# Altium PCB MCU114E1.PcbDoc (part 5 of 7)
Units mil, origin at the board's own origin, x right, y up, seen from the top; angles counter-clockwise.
Board outline 4163.97 x 2322.49 mil, 8 copper layers (Top Layer, GND 2, Signal Layer 3, Power 4, Power 5, Signal Layer 6, GND 7, Bottom), stack 61.2 mil thick; 444 components, 416 nets, 1812 pads, 989 vias.
Unrouted connection lines stored in the file: 3.
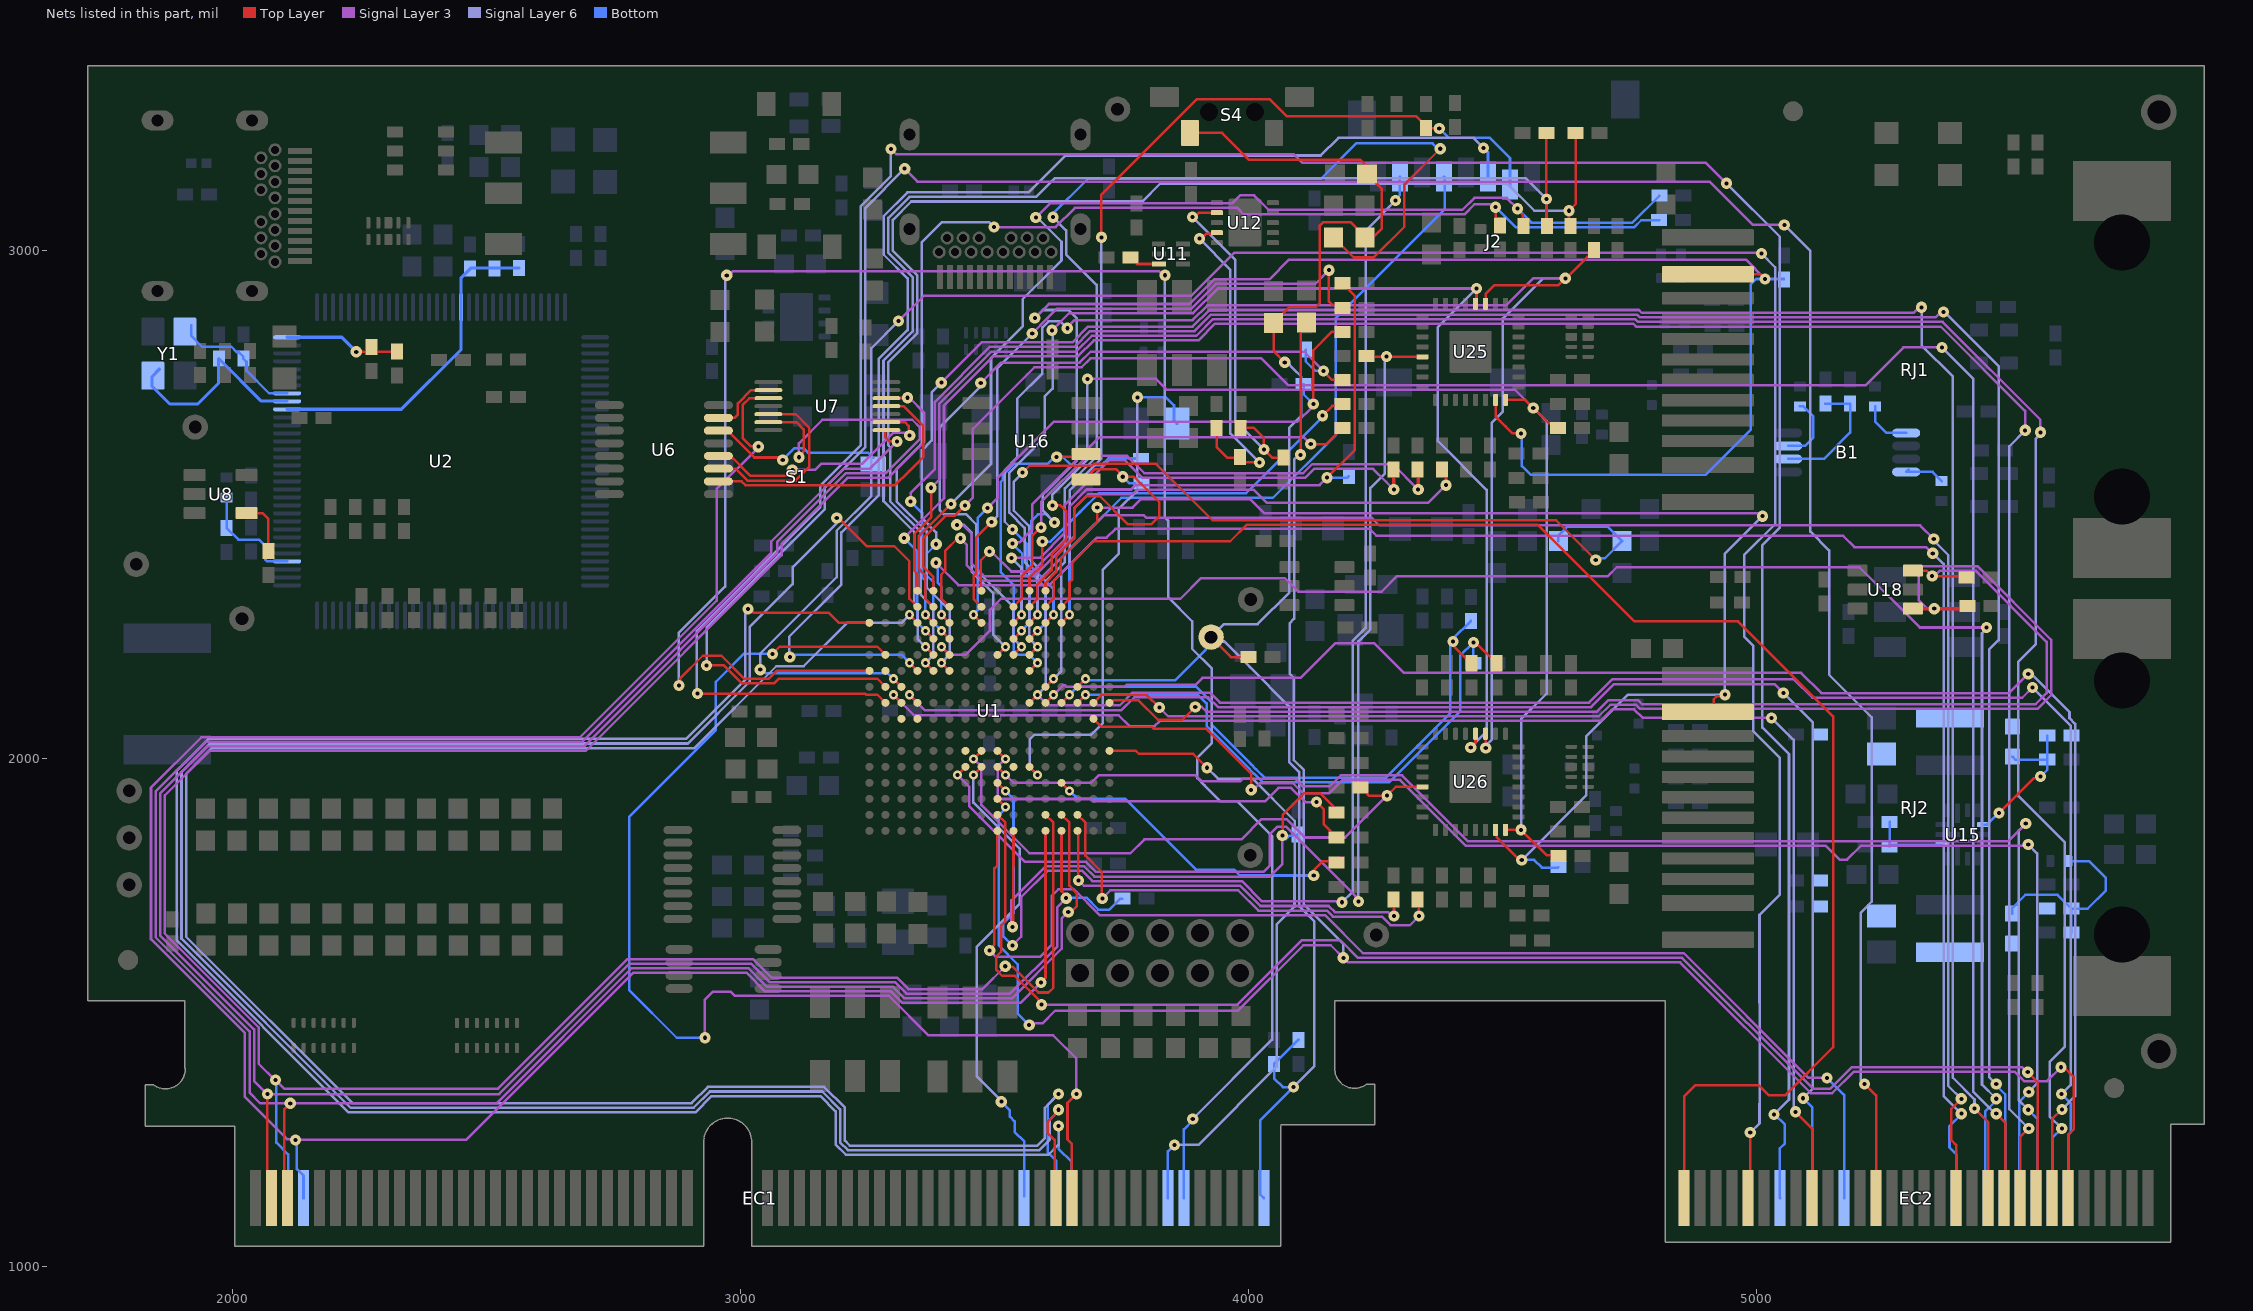
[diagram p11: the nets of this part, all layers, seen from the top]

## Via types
v1: diameter 22, hole 8, Top Layer to Bottom, tented both sides, 818 vias
v2: diameter 18, hole 8, Top Layer to Bottom, tented both sides, 153 vias
v3: diameter 19.68, hole 7.87, Top Layer to Bottom, 18 vias

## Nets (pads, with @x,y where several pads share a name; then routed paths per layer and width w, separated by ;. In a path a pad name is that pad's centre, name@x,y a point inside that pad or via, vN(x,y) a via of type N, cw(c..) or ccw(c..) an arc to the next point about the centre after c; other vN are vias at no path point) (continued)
MCU_GPIO88: EC2.155 U1.B6 | length 3538.7
  Top Layer w5: U1.B6@3411.08,2299.01 3394.54,2315.55 3394.96,2315.96 3394.96,2362.39 3403,2370.44 3403,2409.44 3427.45,2433.89 v1(3432.54,2433.89) ; EC2.155@5391.91,1135.27 5391.91,1240.19 5382.33,1249.77 5382.33,1311.09 v1(5402.04,1330.8)
  Signal Layer 3 w5: v1(3432.54,2433.89) 3445,2421.43 3445,2380.9 3475.44,2350.45 3586.4,2350.45 3715.47,2479.52 3792.83,2479.52 3798.58,2473.77 4242.27,2473.77 4256.77,2459.27 5320.83,2459.27 v1(5347.83,2432.27)
  Signal Layer 6 w5: v1(5347.83,2432.27) 5347.83,2429.02 5376.37,2400.48 5376.37,1356.47 v1(5402.04,1330.8)
MCU_GPIO89: EC2.156 U1.C6 | length 3477.8
  Top Layer w5: v2(3395.33,2283.26) U1.C6@3411.08,2267.52
  Signal Layer 3 w5: v1(3384.42,2385.68) 3428.65,2341.45 3608.02,2341.45 3701.56,2435 3720.45,2435 3737.72,2452.27 4237.83,2452.27 4251.33,2438.77 5169.33,2438.77 5191.83,2416.27 5332.4,2416.27 5344.4,2404.27 v1(5345.83,2404.27)
  Signal Layer 6 w5: v1(5345.83,2404.27) 5346.29,2404.27 5367.37,2383.19 5367.37,1335.98 v1@5399.83,1303.52
  Bottom w5: v1@3388.36,2385.68 3388.36,2346.15 3395.33,2339.18 v2(3395.33,2283.26) ; EC2.156@5391.91,1135.27 5391.91,1222.19 5378.83,1235.27 5378.83,1277.27 5402.04,1300.48 v1(5402.04,1301.54)
MCU_GPIO90: EC2.159 U1.D6 | length 4359.8
  Top Layer w5: v2(3395.33,2251.77) U1.D6@3411.08,2236.02 ; v1(5428,1311.82) 5454.91,1284.92 EC2.159@5454.91,1135.27
  Signal Layer 3 w5: v1(3395,2740) 3474.27,2819.27 3653,2819.27 3684,2850.27 3889.65,2850.27 3922.38,2883 4767.76,2883 4773.31,2877.45 5308.42,2877.45 5319.23,2888.27 v1(5323.83,2888.27)
  Signal Layer 6 w5: v1(3385,2422) 3385,2445.4 3356.83,2473.57 3356.83,2606.83 3375.87,2625.87 3375.87,2720.87 v1(3395,2740) ; v1(5323.83,2888.27) 5323.83,2813.27 5385.37,2751.73 5385.37,1372.27 5428,1329.64 v1(5428,1311.82)
  Bottom w5: v1(3385,2422) 3366.4,2403.4 3366.4,2360.6 3379.33,2347.67 3379.33,2267.76 v2(3395.33,2251.77)
MCU_GPIO91: EC2.160 U1.E6 | length 3393.4
  Top Layer w5: v2(3395.33,2220.27) U1.E6@3411.08,2204.52
  Signal Layer 3 w5: v2(3395.33,2220.27) 3410.83,2204.77 3443.42,2204.77 3490.82,2252.17 3490.82,2292.84 3512.75,2314.77 3865.58,2314.77 3906.13,2355.31 3930.88,2355.31 4070.83,2355.32 4097.6,2328.54 4261.38,2328.54 4292.1,2359.27 4706.56,2359.27 4724.06,2376.77 5202.08,2376.77 5320.58,2258.27 v1(5451.83,2258.27)
  Signal Layer 6 w5: v1(5451.83,2258.27) 5451.83,2255.84 5442.83,2246.84 5442.83,1358.94 v1(5470.83,1330.94)
  Bottom w5: EC2.160@5454.91,1135.27 5449.05,1141.12 5449.05,1305.49 v1@5467.83,1324.27
MCU_GPIO92: EC2.161 U1.A5 | length 4123.5
  Top Layer w5: U1.A5@3379.58,2330.51 3379.58,2357.52 3359.83,2377.27 3359.83,2434.54 3403.11,2477.82 3421.39,2477.82 v1(3441.83,2498.27) ; v1(5470.83,1301.6) 5488.33,1284.1 5488.33,1135.27 EC2.161@5486.4,1135.27
  Signal Layer 3 w5: v1(3441.83,2498.27) 3457.33,2513.77 3457.33,2649.33 3578.27,2770.27 3671,2770.27 3688.5,2787.77 3873.97,2787.77 4024.96,2787.77 4077.96,2734.77 5213.77,2734.77 5288.27,2809.27 v1(5363.83,2809.27)
  Signal Layer 6 w5: v1(5363.83,2809.27) 5425.83,2747.27 5425.83,1344.54 5468.77,1301.6 v1(5470.83,1301.6)
MCU_GPIO93: EC2.162 U1.C5 | length 4348.2
  Top Layer w5: v2(3363.83,2283.26) U1.C5@3379.58,2267.52
  Signal Layer 3 w5: v1(3334.83,2506.27) 3334.83,2522.87 3382.33,2570.37 3382.33,2702.33 3490.27,2810.27 3552.37,2810.27 3656.72,2810.27 3687.72,2841.27 3893.38,2841.27 3926.11,2874 4764.03,2874 4769.58,2868.45 5351.42,2868.45 5362.23,2879.27 v1(5366.83,2879.27)
  Signal Layer 6 w5: v1(5366.83,2879.27) 5368.83,2879.27 5475.37,2772.73 5475.37,2233.54 5456.94,2215.1 5456.94,1374.16 v1(5470.83,1360.27)
  Bottom w5: v1(3334.83,2506.27) 3357.4,2483.7 3357.4,2356.88 3363.83,2350.44 v2(3363.83,2283.26) ; v1@5467.83,1360.27 5488.33,1339.77 5488.33,1137.2 EC2.162@5486.4,1135.27
MCU_GPIO94: EC2.163 U1.D5 | length 4365.5
  Top Layer w5: v2(3363.83,2251.77) U1.D5@3379.58,2236.02 ; EC2.163@5517.9,1135.27 5517.9,1255.33 v1(5534.83,1272.27)
  Signal Layer 3 w5: v1(3322,2434) 3322,2434.19 3400.33,2512.52 3400.33,2694.88 3497.73,2792.27 3544.92,2792.27 3664.18,2792.27 3695.18,2823.27 3900.83,2823.27 3933.56,2856 4756.58,2856 4762.12,2850.45 5361.65,2850.45 5527.83,2684.27 v1(5527.83,2646.27)
  Signal Layer 6 w5: v1(5527.83,2646.27) 5496.37,2614.8 5496.37,1310.73 v1(5534.83,1272.27)
  Bottom w5: v1(3322,2434) 3347.84,2408.16 3347.84,2267.76 v2(3363.83,2251.77)
MCU_GPIO95: EC2.168 U1.A4 | length 4326.5
  Top Layer w5: U1.A4@3348.09,2330.51 3348.09,2363.56 3341.83,2369.81 3341.83,2442 3374.83,2475 v1(3374.83,2533.27)
  Signal Layer 3 w5: v1(3374.83,2533.27) 3391.33,2549.77 3391.33,2698.6 3494,2801.27 3548.65,2801.27 3660.45,2801.27 3691.45,2832.27 3897.1,2832.27 3929.83,2865 4760.3,2865 4765.85,2859.45 5365.37,2859.45 5557.83,2667 v1(5557.83,2642.27)
  Signal Layer 6 w5: v1(5557.83,2642.27) 5557.83,2638.34 5548.33,2628.84 5548.33,2225.02 5514.37,2191.06 5514.37,1926.36 5605.83,1834.9 5605.83,1433.5 5575.83,1403.5 5575.83,1296.27 v1(5599.83,1272.27)
  Bottom w5: EC2.168@5580.89,1135.27 5580.89,1253.33 v1(5599.83,1272.27)
MCU_GPIO96: EC1.93 U1.B4 | length 4396.5
  Top Layer w5: v1(3189.35,2473.79) 3193.04,2473.79 3248.27,2418.55 3302.45,2418.55 3331.96,2389.04 3331.96,2324.14 3331.96,2315.13 U1.B4@3348.09,2299.01 ; EC1.93@3620.35,1135.27 3617.83,1137.79 3617.83,1250.23 3604.33,1263.73 3604.33,1285.15 3625.83,1306.65 v1(3625.83,1309.27)
  Signal Layer 6 w5: v1(3189.35,2473.79) 3187.88,2472.31 3187.88,2462.06 3102.33,2376.52 3102.33,2343.52 3017.83,2259.02 3017.83,2151.54 2896.29,2030 1956.46,2030 1900,1973.54 1900,1645.98 2232.72,1313.27 2907.54,1313.27 2939.54,1345.27 3160.77,1345.27 3196.13,1309.91 3196.13,1244.84 3211.21,1229.77 3587.86,1229.77 3608.29,1250.2 3608.29,1289.1 3625.83,1306.65 v1(3625.83,1309.27)
MCU_GPIO97: EC1.94 U1.C4 | length 4145.2
  Top Layer w5: v2(3332.34,2283.26) U1.C4@3348.09,2267.52
  Signal Layer 6 w5: v2(3332.34,2283.26) 3316.59,2267.51 3209.83,2267.51 3124.31,2182 3070.31,2182 2909.31,2021 1960.18,2021 1909,1969.82 1909,1649.71 2236.44,1322.27 2903.81,1322.27 2935.81,1354.27 3164.5,1354.27 3205.13,1313.64 3205.13,1248.57 3214.93,1238.77 3584.13,1238.77 3598.83,1253.47 3598.83,1313.27 v1(3625.83,1340.27)
  Bottom w5: EC1.94@3620.35,1135.27 3620.83,1135.74 3620.83,1209.27 3604.33,1225.77 3604.33,1318.77 v1(3625.83,1340.27)
MCU_GPIO98: EC1.95 U1.E2 | length 2387.3
  Top Layer w5: v1(3062.83,2206.27) 3077.21,2220.65 3268.97,2220.65 U1.E2@3285.09,2204.52 ; EC1.95@3651.85,1135.27 3651.85,1242.25 3643.33,1250.77 3643.33,1322.77 v1(3660.83,1340.27)
  Signal Layer 3 w5: v1(2930,1451) 2930,1526.19 2945.58,1541.77 2980.5,1541.77 2989,1533.27 3292.58,1533.27 3370.08,1455.77 3615.33,1455.77 3660.83,1410.27 v1(3660.83,1340.27)
  Bottom w5: v1(2930,1451) 2874.46,1451 2780.73,1544.73 2780.73,1885.63 2951.33,2056.24 2951.33,2151.51 3006.09,2206.27 v1(3062.83,2206.27)
MCU_GPIO99: EC1.96 U1.C1 | length 4098.7
  Top Layer w5: v1(3014.84,2294.37) 3019.08,2294.37 3026.27,2287.19 3173.94,2287.19 3193.61,2267.51 U1.C1@3253.6,2267.52
  Signal Layer 6 w5: v1(3014.84,2294.37) 3014.84,2289.77 3008.83,2283.76 3008.83,2155.27 2892.56,2039 1952.73,2039 1891,1977.27 1891,1642.26 2228.99,1304.27 2911.27,1304.27 2943.27,1336.27 3157.05,1336.27 3187.13,1306.18 3187.13,1241.11 3207.48,1220.77 3605.76,1220.77 3625.79,1240.8 v1(3625.79,1277.47) v1@3625.79,1281.86
  Bottom w5: v1@3625.83,1281.81 3625.83,1232.17 3651.85,1206.15 EC1.96@3651.85,1135.27
MCU_GPIO100: J2.3 U1.F4 | length 2558.4
  Top Layer w5: v2(3332.34,2188.77) U1.F4@3348.09,2173.03
  Signal Layer 6 w5: v1@3095.87,2203.69 3095.87,2240.31 3198.33,2342.77 3198.33,2445.29 3272.33,2519.29 3272.33,2787.33 3328.6,2843.6 3328.6,2944.94 3281.83,2991.71 3281.83,3067.83 3328.5,3114.5 3566.5,3114.5 3639,3187 4141.56,3187 4176.33,3221.77 4442.23,3221.77 v1(4462,3202)
  Bottom w5: v1(3096.91,2200.46) 3100.16,2203.72 3107.28,2203.72 3108.34,2204.77 3316.34,2204.77 v2(3332.34,2188.77) ; v1(4462,3202) 4470.75,3193.25 J2.3@4470.75,3145.39
MCU_GPIO101: J2.7 U1.N9 | length 2603.9
  Top Layer w5: U1.N9@3505.57,1952.55 3520.87,1937.25 v2@3520.87,1936.69
  Signal Layer 3 w5: v1(3534.83,1632.69) 3535.12,1632.69 3552.33,1649.89 3552.33,1727.77 3603.75,1779.19 3672.54,1779.19 3692.54,1759.19 3986.54,1759.19 4026.46,1719.27 4182.12,1719.27 v1(4183.76,1717.64)
  Signal Layer 6 w5: v1(4183.76,1717.64) 4204.33,1738.21 4204.33,2232.05 4230.33,2258.05 4230.33,3039.77 v1(4288.83,3098.27)
  Bottom w5: v2(3521.31,1936.81) 3537.06,1921.06 3537.06,1900.78 3537.04,1894.54 ; v1(3534.83,1632.69) 3517.33,1650.19 3517.33,1676.52 3537.06,1696.25 3537.06,1894.52 ; v1(4288.83,3098.27) 4288.83,3100.36 4297.52,3109.05 J2.7@4297.52,3145.39
MCU_GPIO102: J2.5 U1.C13 | length 1365.7
  Top Layer w5: U1.C13@3631.55,2267.52 v2(3647.3,2283.26)
  Bottom w5: v2(3647.3,2283.26) 3647.3,2411.35 3749.09,2513.14 4047.27,2513.14 4171.33,2637.2 4171.33,2798.52 4171.33,2867.33 4385.83,3081.83 4385.83,3099.27 4385.83,3143.7 J2.5@4384.14,3145.39
MCU_GPIO103: J2.2 R36.1 U1.G12 | length 1998.6
  Top Layer w5: U1.G12@3600.06,2141.53 v2(3615.8,2157.28) ; v1(3710,3026) 3710,3109.89 3898.11,3298 4040.81,3298 4074.5,3264.31 4329.2,3264.31 4348.51,3245 R36.1@4348.51,3241.06 4349.31,3240.27 v1(4374.83,3240.27)
  Signal Layer 6 w5: v2(3615.8,2157.28) 3631.3,2172.78 3631.3,2365.42 3647.33,2381.45 3647.33,2527.99 3709.83,2590.49 3709.83,2964.32 3710,2964.49 v1(3710,3026)
  Bottom w5: v1(4374.83,3240.27) 4392.83,3222.27 4473.73,3222.27 4514.06,3181.94 J2.2@4514.06,3129.65
MCU_GPIO104: EC2.121 U1.B13 | length 2980.9
  Top Layer w5: U1.B13@3631.55,2299.01 3647.31,2314.77 3647.3,2347.31 3653.08,2353.09 3653.08,2386.52 3694.56,2428 3963.58,2428 3995.85,2460.27 4568.73,2460.27 4758.73,2270.27 4962.83,2270.27 5149.83,2083.27 5149.83,1432.27 5055.83,1338.27 5022.83,1338.27 5003.18,1357.92 4878.83,1357.92 4856.48,1335.57 EC2.121@4856.48,1135.27
MCU_GPIO105: EC1.108 U1.L16 | length 1295.1
  Top Layer w5: U1.L16@3726.04,2015.55 3777.8,2015.55 3783.58,2009.77 3858.08,2009.77 3890.33,2009.77 v1(3917.83,1982.27)
  Signal Layer 6 w5: v1(3853.83,1240.27) 3901.27,1240.27 4055,1394 4055,1674 4090,1709 4090,1768 4090.33,1768.33 4090.33,1877.99 4007.55,1960.77 3939.33,1960.77 v1(3917.83,1982.27)
  Bottom w5: EC1.108@3840.83,1135.27 3840.83,1227.26 v1(3853.83,1240.27)
MCU_GPIO106: EC1.110 U1.F1 | length 4164.9
  Top Layer w5: v1(2878.83,2144.27) 2881.13,2146.57 2881.13,2158.13 2925.65,2202.65 2962.35,2202.65 3007.81,2157.19 3055.19,2157.19 3071,2173 3225.56,2173 ; 3225.59,2173.03 U1.F1@3253.6,2173.03
  Signal Layer 3 w5: v1(2972.83,2951.27) 2976.53,2951.27 2984.26,2959 3190.25,2959 3190.75,2959.5 3205.25,2959.5 3205.75,2959 3823.84,2959 3831.53,2951.31 v1(3835.27,2951.31)
  Signal Layer 6 w5: v1(2878.83,2144.27) 2878.83,2248.15 2969.5,2338.82 2969.5,2939.84 2969.58,2939.92 2969.58,2948.02 v1(2972.83,2951.27) ; v1(3835.27,2951.31) 3834.65,2950.7 3834.65,2475.17 3842,2467.83 3842,2317.1 3888.83,2270.27 3888.83,2216.02 3927.33,2177.52 3927.33,2031.02 3898.96,2002.65 3898.96,1961.89 3913.33,1947.52 3944.58,1916.27 3977.56,1916.27 4046,1847.83 4046,1447.44 v1(3889.83,1291.27)
  Bottom w5: EC1.110@3872.32,1135.27 3872.32,1270.76 3889.83,1288.27 v1(3889.83,1291.27)
MCU_GPIO107: U1.F2
MCU_GPIO108: EC2.145 U1.G2 | length 5300.7
  Top Layer w5: v1(2933.23,2183.63) 2967.37,2183.63 3002.81,2148.19 3066.17,2148.19 3075.64,2157.65 3268.97,2157.65 U1.G2@3285.09,2141.53 ; v1(5211.83,1360.27) 5234.43,1337.67 EC2.145@5234.43,1135.27
  Signal Layer 3 w5: v1(3323,3161) 3348.23,3135.77 4906.33,3135.77 4991.83,3050.27 v1(5053.83,3050.27)
  Signal Layer 6 w5: v1(2933.23,2183.63) 2933.23,2258.42 3166,2491.19 3166,2534 3245.68,2613.68 3245.68,3083.68 v1(3323,3161) ; v1(5053.83,3050.27) 5105,2999.1 5105,2446.85 5141.83,2410.02 5141.83,2165.27 5225.83,2081.27 5225.83,1718.81 5203.83,1696.81 5203.83,1384.27 5203.83,1368.27 v1(5211.83,1360.27)
MCU_GPIO109: EC2.129 U1.G3 | length 4795.2
  Top Layer w5: v2(3300.84,2157.28) U1.G3@3316.59,2141.53 ; EC2.129@4982.46,1135.27 4986.83,1139.63 v1(4986.83,1264.27)
  Signal Layer 3 w5: v1(3311.1,2861.35) 3360.54,2910.78 3886.52,2910.78 3971.74,2996 5007,2996 v1(5009,2994)
  Signal Layer 6 w5: v1(3038.83,2175.27) 3038.83,2207.02 3189.33,2357.52 3189.33,2449.02 3257.49,2517.18 3257.49,2807.73 v1(3311.1,2861.35) ; v1(4986.83,1264.27) 5005,1282.44 5005,1320.69 5005.33,1321.02 5005.33,1519.21 5005,1519.54 5005,1692.73 5045,1732.73 5045,2001.64 4992.83,2053.81 4992.83,2222.17 4975.33,2239.67 4975.33,2401.52 5036,2462.19 5036,2967 v1(5009,2994)
  Bottom w5: v1(3038.83,2175.27) 3042.99,2175.27 3050.26,2168 3290.12,2168 v2(3300.84,2157.28)
MCU_GPIO110: EC2.134 U1.H2 | length 5382
  Top Layer w5: v1(2915.46,2128.07) 3245.32,2128.07 3247.23,2126.16 3268.97,2126.16 U1.H2@3285.09,2110.03
  Signal Layer 3 w5: v1(3296,3200) 3296.38,3200 3307.2,3189.18 4088.82,3189.18 4105.5,3172.5 4899.6,3172.5 v1(4939.83,3132.27)
  Signal Layer 6 w5: v1(2915.46,2128.07) 2913.83,2129.7 2913.83,2251.75 3157,2494.91 3157,2537.73 3236.68,2617.41 3236.68,3087.41 3296,3146.73 v1(3296,3200) ; v1(4939.83,3132.27) 5045,3027.1 5045,2454.69 5010.83,2420.52 5010.83,2061.27 5050.33,2021.77 5063,2009.1 5063,1329.44 v1(5033.83,1300.27)
  Bottom w5: v1(5033.83,1300.27) 5034.83,1300.27 5054.83,1280.27 5054.83,1243.27 5044.83,1233.27 5044.83,1135.89 EC2.134@5045.46,1135.27
MCU_GPIO111: EC2.137 U1.H3 | length 2774.7
  Top Layer w5: v2(3300.84,2125.78) U1.H3@3316.59,2110.03 ; v1(5075.83,1305.27) 5108.45,1272.65 EC2.137@5108.45,1135.27
  Signal Layer 3 w5: v2(3300.84,2125.78) 3341.1,2085.52 3743.83,2085.52 3765.36,2064 3814.83,2064 3825.41,2074.58 4692.41,2074.58 4715.1,2097.27 4758.42,2097.27 4775.42,2080.27 v1(5028.83,2080.27)
  Signal Layer 6 w5: v1(5028.83,2080.27) 5072,2037.1 5072,1316.7 5072.58,1316.12 5072.58,1308.52 v1(5075.83,1305.27)
MCU_GPIO112: EC2.138 U1.H4 | length 2832.7
  Top Layer w5: v2(3332.34,2125.78) U1.H4@3348.09,2110.03
  Signal Layer 3 w5: v2(3332.34,2125.78) 3363.09,2095.03 3748.84,2095.03 3774.81,2121 3920.27,2121 3939.69,2101.58 4673.43,2101.58 4718.85,2147 5034.1,2147 v1(5051.83,2129.27)
  Signal Layer 6 w5: v1(5051.83,2129.27) 5110,2071.1 5110,1351 v1(5091,1332)
  Bottom w5: v1(5091,1332) 5108.45,1314.55 EC2.138@5108.45,1135.27
MCU_GPIO113: U1.J3 | length 0
MCU_GPIO114: U1.J4
MCU_GPIO115: EC2.169 R212.1 U1.P9 | length 4320.1
  Top Layer w5: U1.P9@3505.57,1921.06 v2(3521.31,1905.31) ; v1(4102,2598) 4102,2846.18 R212.1@4113.87,2858.05 ; v1(5598,1393) 5604.1,1393 5623,1374.1 5623,1270.69 5612.39,1260.07 EC2.169@5612.39,1135.27
  Signal Layer 3 w5: v1(3568,1476) 3571.25,1479.25 3594.25,1479.25 3619.27,1504.27 3979,1504.27 4107.73,1633 4161.33,1633 v1(4186.06,1608.27) 4195.06,1599.27 4848.83,1599.27 5106.33,1341.77 5148.06,1341.77 5190.56,1384.27 5507.08,1384.27 5525.58,1365.77 5570.77,1365.77 v1(5598,1393)
  Signal Layer 6 w5: v1(4102,2598) 4098.68,2598 4089.33,2588.65 4089.33,2275.52 4080.33,2266.52 4080.33,2167.67 4088.59,2159.41 4088.59,1997.45 4108.33,1977.71 4108.33,1760.54 4108,1760.21 4108,1713.83 4186.06,1635.77 v1(4186.06,1608.27)
  Bottom w5: v2(3521.31,1905.31) 3521.31,1901.79 3507.8,1888.28 3507.8,1633.2 3545.4,1595.6 3545.4,1498.6 v1(3568,1476)
MCU_GPIO116: EC2.170 R78.1 U1.H11 | length 5316.3
  Top Layer w5: U1.H11@3568.56,2110.03 v2(3584.31,2125.78) ; R78.1@4168.13,3024.77 4206.63,2986.27 4245.83,2986.27 4306.33,3046.77 4306.33,3129.77 v1(4376.83,3200.27)
  Signal Layer 3 w5: v2(3584.31,2125.78) 3604.86,2105.22 3746.31,2105.22 3771.09,2130 3924,2130 3943.42,2110.58 4669.7,2110.58 4715.12,2156 5073,2156 5109,2120 5522,2120 v1(5542,2140)
  Signal Layer 6 w5: v2(3584.31,2125.78) 3600.3,2141.78 3600.3,2349.05 3638.33,2387.07 3638.33,2531.72 3700.83,2594.22 3700.83,2932.17 3640.53,2992.47 3640.53,3039.69 v1(3614.58,3065.64) ; v1(5542,2140) 5617,2065 5617,1358 v1(5599,1340)
  Bottom w5: v1@3611.11,3069.11 3683.27,3141.27 4141.83,3141.27 4211.33,3210.77 4361.73,3210.77 4372.23,3200.27 v1(4376.83,3200.27) ; v1(5599,1340) 5617.5,1321.5 5617.5,1265.19 5612.39,1260.07 EC2.170@5612.39,1135.27
MCU_GPIO119: U1.M10
MCU_GPIO120: R85.2 U1.M11 | length 1042
  Top Layer w5: U1.M11@3568.56,1984.05 v2(3584.31,1968.3)
  Signal Layer 6 w5: v2(3584.31,1968.3) 3568.81,1983.8 3568.81,2037.71 3577.89,2046.79 3685.21,2046.79 3689.63,2046.79 3712.83,2070 3712.83,2372 3744.1,2403.27 3744.1,2491.17 3780.78,2527.85 v1(3780.78,2711.18)
  Bottom w5: v1(3780.78,2711.18) 3837.07,2711.18 3852.91,2695.34 3852.91,2665.19 R85.2@3858.83,2659.27
MCU_GPIO122: U1.L7 | length 0
MCU_GPIO123: R108.2 U1.M7 U25.21 | length 2255.2
  Top Layer w5: v2(3426.83,1968.3) U1.M7@3442.57,1984.05 ; R108.2@4232.06,2792.69 4233.9,2790.84 U25.21@4341.95,2790.84
  Signal Layer 3 w5: v2(3426.83,1968.3) 3449.83,1945.3 3449.83,1907.27 3559.91,1797.19 3679.99,1797.19 3699.68,1777.5 3953.58,1777.5 3953.89,1777.19 4029,1777.19 4041.57,1789.76 4041.57,1851.77 4056.3,1866.5 4073.25,1866.5 4210.07,1729.67 ; 4210.07,1729.63 4215.83,1723.87 v1(4215.83,1719.27)
  Signal Layer 6 w5: v1(4215.83,1719.27) 4215.83,2230.82 4239.33,2254.32 4239.33,2532.77 4267.94,2561.37 4267.94,2788.37 v1(4270.83,2791.27)
MCU_GPIO124: R142.2 U1.L8 U26.21 | length 1172.1
  Top Layer w5: v2(3458.32,1999.8) U1.L8@3474.07,2015.55 ; R142.2@4219.5,1942.8 4223.44,1942.8 4232.75,1933.49 4232.75,1930.2 4235.68,1927.27 v1(4271.83,1927.27) 4289.41,1944.84 U26.21@4341.95,1944.84
  Signal Layer 3 w5: v2(3458.32,1999.8) 3473.82,1984.3 3473.82,1908.55 3568.37,1814 3767,1814 3794.45,1841.45 3985.45,1841.45 4025.27,1881.27 4074.31,1881.27 4110.54,1845.03 4189.6,1845.03 v1(4271.83,1927.27)
MCU_GPIO125: EC1.90 U1.M8 | length 964.2
  Top Layer w5: v2(3458.32,1968.3) U1.M8@3474.07,1984.05
  Signal Layer 6 w5: v2(3458.32,1968.3) 3458.32,1913.53 3549.83,1822.02 3549.83,1715.27 3464.37,1629.81 3464.37,1375.61 3513.11,1326.88 v1(3513.11,1325.18)
  Bottom w5: v1(3513.11,1325.18) 3530.03,1308.26 3530.03,1295.63 3539.33,1286.33 3539.33,1265.77 3558.43,1246.67 EC1.90@3558.43,1138.69
MCU_GPIO126: EC2.142 U1.T9 | length 2410.3
  Top Layer w5: v1(3490.3,1622.75) 3490.3,1625.11 3499.37,1634.18 3499.37,1784.02 3505.57,1790.22 U1.T9@3505.57,1858.07
  Signal Layer 3 w5: v1(3490.3,1622.75) 3502.79,1610.27 3588.83,1610.27 3612.83,1634.27 3612.83,1730.54 3625.48,1743.19 3655.81,1743.19 3706.73,1692.27 4149.83,1692.27 4224.83,1617.27 4856.29,1617.27 5101.56,1372 v1(5138,1372)
  Bottom w5: v1(5138,1372) 5171.44,1338.56 EC2.142@5171.44,1135.27
MCU_GPIO127: EC2.165 U1.R9 | length 2833.4
  Top Layer w5: U1.R9@3505.57,1889.56 3520.94,1874.19 3520.94,1680.13 3513,1672.19 3513,1620.71 3503.37,1611.08 3503.37,1584.44 3514.81,1573 3539.1,1573 3592,1520.1 v1(3592,1516) ; v1(5532.83,1383.27) 5552.33,1363.77 5552.33,1135.27 EC2.165@5549.39,1135.27
  Signal Layer 3 w5: v1(3592,1516) 3978,1516 4105,1643 4180,1643 4214.73,1608.27 4852.56,1608.27 5110.06,1350.77 5144.33,1350.77 5186.83,1393.27 5521.4,1393.27 5531.4,1383.27 v1(5532.83,1383.27)
MCU_GPIO128: EC2.166 U1.M9 | length 2891.6
  Top Layer w5: U1.M9@3505.57,1984.05 v2(3521.31,1968.3)
  Signal Layer 3 w5: v2(3521.31,1968.3) 3536.81,1952.8 3690.12,1952.8 3704.59,1967.27 3895.35,1967.27 3906.85,1955.77 3983.33,1955.77 3988.33,1960.77 4090.81,1960.77 4105.98,1945.61 4159.37,1945.61 4181.04,1967.27 4301.56,1967.27 4431.33,1837.5 5494.06,1837.5 v1(5528.83,1872.27)
  Signal Layer 6 w5: v1(5528.83,1872.27) 5515.33,1858.77 5515.33,1334.27 5515.33,1327.77 v1(5533.83,1309.27)
  Bottom w5: v1(5533.83,1309.27) 5552.33,1290.77 5552.33,1138.21 EC2.166@5549.39,1135.27
MCU_GPIO129: R91.2 U1.L9 | length 844.1
  Top Layer w5: U1.L9@3505.57,2015.55 v2(3521.31,1999.8) ; v1(4133.35,1914.68) 4147.33,1900.7 4147.33,1871.5 R91.2@4171.71,1847.13 ; R91.2@4180.88,1852.02 R91.2@4184.81,1852.02
  Signal Layer 3 w5: 3505.81,1979.12 3505.81,1925.97 3510.98,1920.81 3690.26,1920.81 3694.8,1916.27 4031.93,1916.27 4058.43,1942.77 4068.58,1942.77 4083.36,1942.77 4111.45,1914.68 v1(4133.35,1914.68) ; 3505.83,1979.14 3505.83,1984.31 v2(3521.31,1999.8)
MCU_GPIO130: R146.2 R155.1 U1.T10 | length 1087.9
  Top Layer w5: v1(3534.83,1669.27) 3536.83,1671.27 3536.83,1789.08 3537.06,1789.32 U1.T10@3537.06,1858.07 ; v1@4066.54,1849 4066.54,1889.41 4109.4,1932.27 4109.49,1932.18 4140.6,1932.18 4171.71,1901.07 R155.1@4171.71,1894.55
  Signal Layer 3 w5: v1(3534.83,1669.27) 3532.95,1671.15 3532.95,1721.11 3600.02,1788.19 3676.26,1788.19 3696.26,1768.19 4041.64,1768.19 4066,1792.54 v1(4066,1849)
  Bottom w5: v1@4073,1842 4079.85,1848.85 4093.74,1848.85 R146.2@4096.24,1851.36
MCU_GPIO131: R203.2 U1.N13 | length 647.8
  Top Layer w5: U1.N13@3631.55,1952.55 v2(3647.3,1936.81) ; v1(4127.83,1770.27) 4127.83,1780.36 4146.12,1798.64 4170.65,1798.64 R203.2@4171.71,1799.7 ; R203.2@4173.8,1797.61 4180.88,1804.69 R203.2@4184.81,1804.69
  Bottom w5: v2(3647.3,1936.81) 3662.74,1921.37 3672.31,1921.37 3672.37,1921.31 3685.21,1921.31 3685.28,1921.37 3756.36,1921.37 3895.81,1781.92 3970.64,1781.92 3982.29,1770.27 v1(4127.83,1770.27)
MCU_GPIO132: R144.2 U1.T14 | length 782.1
  Top Layer w5: U1.T14@3663.05,1858.07 3664.59,1856.52 3664.59,1761.97 v1@3665.87,1760.69 ; R144.2@4284.44,1723.06 4285.83,1721.67 v1(4285.83,1690.27)
  Signal Layer 3 w5: v1(3664.87,1760.69) 3675.37,1750.19 3982.81,1750.19 4022.73,1710.27 4157.29,1710.27 4169.29,1698.27 4274.4,1698.27 4282.4,1690.27 v1(4285.83,1690.27)
MCU_GPIO133: EC2.164 U1.J15 | length 2730.8
  Top Layer w5: U1.J15@3694.54,2078.54 3710.29,2062.79 3809.75,2062.79 3813.8,2058.75 3917.25,2058.75 4004.74,1971.26 v1(4004.74,1938.83)
  Signal Layer 3 w5: v1@4009.75,1939.35 4022.17,1951.77 4087.09,1951.77 4106.59,1932.27 4158.76,1932.27 4184.76,1958.27 4297.83,1958.27 4427.6,1828.5 5135.75,1828.5 5162.75,1801.5 5177.25,1801.5 5204.25,1828.5 5531.06,1828.5 v1(5533.83,1831.27)
  Signal Layer 6 w5: v1(5533.83,1831.27) 5551.33,1813.77 5551.33,1360.77 v1(5534.83,1344.27)
  Bottom w5: EC2.164@5517.9,1135.27 5516.33,1136.83 5516.33,1325.77 v1(5534.83,1344.27)
MCU_GPIO134: R110.2 U1.R14 | length 887.3
  Top Layer w5: U1.R14@3663.05,1889.56 3678.42,1874.19 3678.42,1809.58 3710.35,1777.65 3710.35,1726.75 v1(3711.83,1725.27) ; v1@4332.44,1692.66 v1(4334.83,1690.27) 4334.83,1720.67 R110.2@4332.44,1723.06
  Signal Layer 3 w5: v1(3711.83,1725.27) 3727.75,1741.19 3979.09,1741.19 4019,1701.27 4153.56,1701.27 4165.56,1689.27 4262.08,1689.27 4278.58,1672.77 4279.33,1672.77 4279.83,1672.27 4316.83,1672.27 v1(4334.83,1690.27)
MCU_GPIO141: R145.1 R152.1 U1.H13 | length 1178.6
  Top Layer w5: U1.H13@3631.55,2110.03 v2(3647.3,2125.78) ; v1(4402.18,2230.49) 4405.2,2227.48 4405.2,2220.26 4431.79,2193.67 R152.1@4431.79,2189.33
  Bottom w5: v2(3647.3,2125.78) 3663.29,2141.78 3896.63,2141.78 3927.33,2111.08 3927.33,2066.44 4004.15,1989.63 4004.15,1989.3 4014.4,1979.05 4014.72,1979.05 4030.78,1963 4270.09,1963 4396.83,2089.75 v1@4396.83,2228.27 ; v1(4402.18,2230.49) 4402.18,2236.56 R145.1@4437,2271.38
MCU_GPIO142: R133.1 R153.1 U1.H14 | length 1164.6
  Top Layer w5: U1.H14@3663.05,2110.03 v2(3678.79,2125.78) ; v1(4442,2229) 4446.22,2229 R153.1@4487.33,2187.89
  Bottom w5: v2(3678.79,2125.78) 3899.9,2125.78 3917,2108.69 3917,2064.05 3995.15,1985.9 3995.15,1985.58 4010.67,1970.05 4011,1970.05 4027.05,1954 4276.64,1954 4415.91,2093.27 4415.91,2202.91 v1(4442,2229) 4442.06,2228.94 R133.1@4442.06,2187.89
MCU_GPIO145: R139.1 U1.H15 U18.1 | length 2571
  Top Layer w5: U1.H15@3694.54,2110.03 3710.29,2125.78 3799.22,2125.78 v1(3824,2101)
  Top Layer w6.25: U18.1@5306.57,2295.28 v1(5348.83,2295.27) 5408.4,2295.27 R139.1@5413.81,2300.69
  Signal Layer 3 w5: v1(3824,2101) 3824,2100.82 3841.24,2083.58 4688.69,2083.58 4711.38,2106.27 4762.15,2106.27 4770.15,2098.27 5551.83,2098.27 5579,2125.44 5579,2233.83 5433.74,2379.09 5326.94,2379.09 5317.94,2370.09 5317.94,2312.45 5333.89,2296.49 5347.61,2296.49 v1(5348.83,2295.27)
MCU_GPIO146: R140.1 U1.H16 U18.3 | length 2397.3
  Top Layer w5: U1.H16@3726.04,2110.03 3728.95,2110.03 3733.68,2114.77 3783.23,2114.77 3821.25,2076.75 3869.33,2076.75 v1(3894.67,2102.09) ; U18.3@5306.57,2370.09 5333.75,2370.09 5344.57,2359.27 5409.23,2359.27 R140.1@5411.81,2356.69
  Signal Layer 3 w5: v1(3894.67,2102.09) 3907.49,2102.09 3917,2092.58 4684.96,2092.58 4707.65,2115.27 4765.88,2115.27 4773.88,2107.27 5548.1,2107.27 5570,2129.17 5570,2230.1 5430.01,2370.09 5360.18,2370.09 5349.36,2359.27 v1(5344.83,2359.27)
MCU_GPIO147: EC2.167 U1.H12 | length 3133
  Top Layer w5: U1.H12@3600.06,2110.03 v2(3615.8,2125.78) ; EC2.167@5580.89,1135.27 5580.89,1291.21 5599.68,1310 v1(5600,1310)
  Signal Layer 3 w5: v2(3615.8,2125.78) 3634.27,2144.25 3638.41,2144.25 3640.88,2141.78 3756.01,2141.78 3760,2145.77 3895.77,2145.77 3909,2159 4102,2159 4170.35,2227.35 4246.56,2227.35 4305.14,2168.77 4985.99,2168.77 4986.22,2169 5087,2169 5127,2129 5496.12,2129 v1(5533.74,2166.62)
  Signal Layer 6 w5: v1(5533.74,2166.62) 5540.13,2166.62 5615,2091.75 5615,2079.73 5626,2068.73 5626,1336 v1(5600,1310)
MCU_GPIO148: R129.2 RJ1.2 U1.C12 U25.31 | length 3446.1
  Top Layer w5: U1.C12@3600.06,2267.52 v2(3615.8,2283.26) ; U25.31@4485.65,2706.2 4485.65,2673.7 4505.58,2653.77 4519.08,2640.27 v1(4535.83,2640.27) ; RJ1.2@4903.31,2953.48 5006.52,2953.48 v1(5016,2944)
  Signal Layer 3 w5: v1(3579,2867) 3606.77,2894.77 3883.24,2894.77 3931.74,2943.27 4040.83,2943.27 4079.56,2982 4978,2982 v1(5016,2944)
  Signal Layer 6 w5: v1(3579,2867) 3595,2883 3645.1,2883 3661.86,2866.24 3661.86,2586.74 3594.83,2519.71 3594.83,2488.17 3617.83,2465.17 v1(3617.83,2464.62)
  Bottom w5: v2(3615.8,2283.26) 3615.8,2333.72 3572.51,2377.01 3572.51,2411.05 3572.51,2467.95 3585.32,2480.76 3601.69,2480.76 v1(3617.83,2464.62) ; v1(4535.83,2640.27) 4537.44,2638.66 4537.44,2576.01 4555,2558.46 4898.39,2558.46 4988.21,2648.27 4988.21,2934 4998.21,2944 v1(5016,2944) 5052.28,2944 R129.2@5052.92,2943.36
MCU_GPIO149: R163.1 RJ2.2 U1.B12 U26.31 | length 2788.6
  Top Layer w5: U1.B12@3600.06,2299.01 3616.18,2315.13 3616.18,2349.61 3630.05,2363.49 3630.05,2394.1 3701.83,2465.88 v1(3701.83,2494.27) ; U26.31@4485.65,1860.2 4487.65,1858.2 4487.65,1846.01 4532.63,1801.03 v1(4537.23,1801.03) ; RJ2.2@4922.62,2091.83 RJ2.2@4903.31,2091.83 4915,2103.52 4915,2117 4920.75,2122.75 4933.75,2122.75 v1(4937,2126)
  Signal Layer 3 w5: v1(3701.83,2494.27) 3771.27,2494.27 3787.77,2510.77 4002.79,2510.77 4030.79,2482.77 5000.73,2482.77 5006.23,2477.27 v1(5010.83,2477.27)
  Signal Layer 6 w5: v1(4537.23,1801.03) 4664,1927.8 4664,2044.19 4745.81,2126 v1(4937,2126) 4937,2403.44 v1(5010.83,2477.27)
  Bottom w5: v1(4537.23,1801.03) 4561.28,1801.03 4576.69,1785.61 4608.21,1785.61 R163.1@4609.21,1786.61
MCU_GPIO150: R105.1 U1.A12 U16.5 | length 644.6
  Top Layer w5: U1.A12@3600.06,2330.51 3600.06,2346.22 3621.05,2367.21 3621.05,2397.83 3656.33,2433.11 3656.33,2492.52 3680.58,2516.77 3706.85,2516.77 3762.35,2461.27 3807.83,2461.27 3823.96,2477.39 3823.96,2504.69 3773.73,2554.92 v1(3752.08,2554.92) 3752.08,2556.51 3738.59,2570 3697.52,2570 3679.87,2552.35 U16.5@3679.87,2549.69
  Bottom w5: v1(3752.08,2554.92) 3765,2542 R105.1@3789.38,2542
MCU_GPIO151: R106.1 U1.F11 U16.6 | length 788.7
  Top Layer w5: U1.F11@3568.56,2173.03 v2(3584.31,2188.77) ; v1(3622.03,2594) 3674.19,2594 U16.6@3679.87,2599.69
  Bottom w5: v2(3584.31,2188.77) 3568.81,2204.27 3546.89,2204.27 3537.31,2213.85 3537.31,2342 3511.83,2367.48 3511.83,2544.53 3515.9,2548.6 3515.9,2557.59 3539.02,2580.71 3604.77,2580.71 3618.06,2594 v1(3622.03,2594) 3634.05,2594 3650.37,2577.68 3710.41,2577.68 3723.73,2591 3776.48,2591 3777.21,2590.27 R106.1@3773.27,2590.27
MCU_GPIO152: U1.E11 U25.12 U26.12 | length 2621.2
  Top Layer w5: U1.E11@3568.56,2204.52 v2(3584.31,2220.27)
  Top Layer w6.25: v1(4436.83,2022.27) 4446.28,2031.72 U26.12@4446.28,2049.17 ; U25.12@4446.28,2895.17 4447.83,2896.73 v1(4447.83,2925.27)
  Signal Layer 3 w5: v1(3613,2843) 3646.77,2876.77 3890.69,2876.77 3939.19,2925.27 v1(4447.83,2925.27)
  Signal Layer 6 w5: v2(3584.31,2220.27) 3568.31,2236.27 3568.31,2377.52 3558.83,2387 3558.83,2454.27 3528.83,2484.27 3528.83,2562.83 3599,2633 3599,2713.48 3614,2728.48 3614,2842 v1(3613,2843) ; v1(4436.83,2022.27) 4468,2053.44 4468,2529.1 4372,2625.1 4372,2849.44 v1(4447.83,2925.27)
MCU_GPIO153: R107.1 U1.D11 U25.11 U26.11 | length 3084.5
  Top Layer w5: U1.D11@3568.56,2236.02 v2(3584.31,2251.77) ; U26.11@4465.96,2049.17 4466.34,2048.8 v1(4466.34,2021.19) ; U25.11@4465.96,2895.17 4465.96,2914.4 4482.83,2931.27 4608.45,2931.27 v1@4622.64,2945.46 ; v1(4622.83,2945.27) 4624.25,2945.27 4666.38,2987.4 4670.32,2987.4 4679.63,2996.71 R107.1@4679.63,3000.65
  Signal Layer 3 w5: v1(3643,2847) 3643,2849.3 3656.7,2863 3889.65,2863 3918.65,2892 4506.37,2892 4559.64,2945.27 v1(4622.83,2945.27)
  Signal Layer 6 w5: v1(3534.83,2451.27) 3519.83,2466.27 3519.83,2568.1 3544.33,2592.6 3544.33,2708.31 3594,2757.98 3594,2848.75 3605.75,2860.5 3629.5,2860.5 v1(3643,2847) ; v1(4466.34,2021.19) 4466.34,2025.79 4477.83,2037.28 4477.83,2661.02 4500,2683.19 4500,2866.44 4578.83,2945.27 v1(4622.83,2945.27)
  Bottom w5: v1(3534.83,2451.27) 3563.33,2422.77 3563.33,2373.46 3599.81,2336.98 3599.81,2267.27 v2(3584.31,2251.77)
MCU_GPIO154: R59.1 R64.1 U1.C11 | length 1763.6
  Top Layer w5: v1(3555,2563) 3568.5,2576.5 3691.3,2576.5 3695.17,2580.37 3817.73,2580.37 3928.83,2469.27 4604.83,2469.27 v1(4682.83,2391.27) ; U1.C11@3568.56,2267.52 v2(3584.31,2283.26)
  Signal Layer 6 w5: v1(3555,2563) 3555,2562.31 3537.83,2545.14 3537.83,2488 3567.83,2458 3567.83,2393.77 3584.31,2377.29 v2(3584.31,2283.26)
  Bottom w5: R59.1@4609.44,2428.17 4609.44,2438.9 4627.31,2456.77 4705.84,2456.77 R64.1@4734.44,2428.17 4700.78,2394.52 4686.08,2394.52 v1(4682.83,2391.27)
MCU_GPIO155: R32.1 R141.1 U1.B11 U25.32 U26.32 | length 2539.4
  Top Layer w5: U1.B11@3568.56,2299.01 3583.93,2314.39 3583.93,2342.83 3612.05,2370.94 3612.05,2401.55 3641.33,2430.84 3641.33,2486.52 3629.33,2498.52 v1(3613.58,2498.52) ; U26.32@4505.33,1860.2 v1(4535.92,1860.2) 4586.44,1809.69 R141.1@4608.81,1809.69 ; U25.32@4505.33,2706.2 4543.9,2706.2 4590.33,2659.77 4604.73,2659.77 R32.1@4608.81,2655.69
  Signal Layer 3 w5: v1(3682.58,2747.34) 3817.89,2747.34 3839.46,2725.77 4524.33,2725.77 v1(4559.83,2690.27)
  Signal Layer 6 w5: v1(3613.58,2498.52) 3613.58,2519.7 3682.58,2588.7 v1(3682.58,2747.34) ; v1(4535.92,1860.2) 4535.92,2077.92 4586.33,2128.33 4586.33,2663.77 v1(4559.83,2690.27)
MCU_GPIO156: R58.2 U1.A11 | length 811.9
  Top Layer w5: U1.A11@3568.56,2330.51 3568.56,2356.1 3593.83,2381.37 v1(3593.83,2427.27) ; v1(4145,2675) 4164.49,2694.49 4181.29,2694.49 R58.2@4184.81,2698.02
  Bottom w5: v1(3593.83,2427.27) 3609.52,2427.27 3667.75,2485.5 3668.31,2485.5 3705.24,2522.43 3994.99,2522.43 4016.33,2543.77 4145,2672.44 v1(4145,2675)
MCU_GPIO157: R112.2 R120.1 U1.E10 | length 1493.4
  Top Layer w5: U1.E10@3537.06,2204.52 v2(3552.81,2220.27) ; v1@4147.83,2761.27 4163.75,2745.35 R120.1@4184.81,2745.35 R120.1@4182.15,2742.69
  Signal Layer 3 w5: v1(3472.7,2739.43) 3512.55,2779.27 3667.27,2779.27 3688.77,2800.77 4109.23,2800.77 v1(4147,2763)
  Signal Layer 6 w5: v1@3476.07,2736.07 3392.33,2652.33 3392.33,2488.68 3400.24,2480.77 3444.23,2480.77 3463.83,2461.17 3463.83,2371.81 3536.78,2298.86 3536.78,2289.71 3536.81,2245.35 ; 3536.78,2245.31 3536.78,2236.3 v2(3552.81,2220.27)
  Bottom w5: R112.2@4112.21,2804.9 4112.21,2781.79 4131,2763 v1(4147,2763)
MCU_GPIO158: R87.2 U1.D10 | length 999.2
  Top Layer w5: U1.D10@3537.06,2236.02 v2(3552.81,2251.77) ; v1(4122,2619) 4153.13,2619 R87.2@4184.81,2650.69
  Signal Layer 3 w5: v1(3534.83,2423.27) 3537.22,2425.66 3548.6,2425.66 3573.88,2450.94 3573.88,2500.3 3706.59,2633 4108,2633 v1(4122,2619)
  Bottom w5: v1(3534.83,2423.27) 3549.21,2408.89 3549.21,2408.64 3554.33,2403.52 3554.33,2369.73 3568.81,2355.26 3568.81,2267.76 v2(3552.81,2251.77)
MCU_GPIO159: R86.2 U1.C10 | length 1084.4
  Top Layer w5: U1.C10@3537.06,2267.52 v2(3552.81,2283.26)
  Top Layer w6.25: R86.2@4284.44,2569.06 4285.44,2568.06 v1(4285.44,2529.69)
  Signal Layer 3 w5: v1(3533.33,2395.18) 3588.82,2395.18 3637.83,2444.19 3637.83,2499.47 3725.36,2587 3756.83,2587 3791.06,2552.77 4110.77,2552.77 4128.5,2570.5 4244.62,2570.5 4270.12,2545 v1(4285.44,2529.69)
  Signal Layer 6 w5: v1(3533.33,2395.18) 3552.81,2375.69 v2(3552.81,2283.26)
MCU_GPIO160: R84.2 U1.B10 | length 1091.1
  Top Layer w5: U1.B10@3537.06,2299.01 3552.98,2314.93 3552.98,2359.29 3574.33,2380.64 3574.33,2439.5 3590.04,2455.2 v1(3591.38,2455.2)
  Top Layer w6.25: R84.2@4332.12,2569.06 4333.44,2567.74 v1(4333.44,2529.69)
  Signal Layer 3 w5: v1(3591.38,2455.2) 3591.38,2505.07 3682.31,2596 3760.56,2596 3794.79,2561.77 4107.04,2561.77 4124.77,2579.5 4283.62,2579.5 v1(4333.44,2529.69)
MCU_GPIO161: R83.2 U1.E9 | length 1510.4
  Top Layer w5: U1.E9@3505.57,2204.52 v2(3521.31,2220.27)
  Top Layer w6.25: R83.2@4379.8,2569.06 4387.83,2561.03 v1(4387.83,2538.27)
  Signal Layer 3 w5: v1(3425.58,2460.32) 3427.82,2458.08 3439.5,2458.08 3454.83,2442.75 3454.83,2383.79 3479.17,2359.45 3578.55,2359.45 3656.33,2437.24 3656.33,2492.52 3684.58,2520.77 3772.31,2520.77 3780.89,2529.35 4009.67,2529.35 4035.25,2503.77 4353.33,2503.77 v1(4387.83,2538.27)
  Signal Layer 6 w5: v1(3425.58,2460.32) 3439.41,2460.32 3454.83,2444.9 3454.83,2368.08 3496.81,2326.1 3496.81,2244.77 v2(3521.31,2220.27)
MCU_GPIO162: R115.1 R127.2 U1.A8 | length 1325
  Top Layer w5: U1.A8@3474.07,2330.51 3472.65,2331.93 3472.65,2390.34 v1(3489.83,2407.52) ; v1(4154,2553) 4208.81,2607.81 4208.81,2910.69 R115.1@4184.81,2934.69
  Signal Layer 3 w5: v1@3496.28,2405.02 3532.84,2368.45 3574.82,2368.45 3646.83,2440.46 3646.83,2495.75 3680.85,2529.77 3768.58,2529.77 3777.16,2538.35 4139.35,2538.35 v1(4154,2553)
  Bottom w5: v1(4154,2553) 4194,2553 R127.2@4197,2556
MCU_GPIO163: R114.1 U1.B8 | length 1321.1
  Top Layer w5: U1.B8@3474.07,2299.01 3458.7,2314.39 3458.7,2359.49 3463.65,2364.44 3463.65,2435.34 v1(3494.14,2465.83) ; v1(4157.83,2961.27) 4157.83,2899.66 4164.49,2893 4179.17,2893 R114.1@4184.81,2887.35
  Signal Layer 3 w5: v1(3574,2837) 3604,2867 3622.77,2885.77 3886.96,2885.77 3935.46,2934.27 4130.83,2934.27 v1(4157.83,2961.27)
  Signal Layer 6 w5: v1(3494.14,2465.83) 3494.14,2466.14 3505,2477 3505,2768 v1(3574,2837)
MCU_GPIO164: R88.1 R119.1 U1.C8 | length 1220.4
  Top Layer w5: v2(3458.32,2283.26) U1.C8@3474.07,2267.52 ; v1(4127,2698) 4127,2803.81 4163.21,2840.02 R119.1@4184.81,2840.02
  Signal Layer 3 w5: v1(3485.83,2493.27) 3505.83,2513.27 3505.83,2552.56 3616.04,2662.77 4095.33,2662.77 4127,2694.44 v1(4127,2698)
  Bottom w5: v2(3458.32,2283.26) 3458.32,2284.68 3466.33,2292.69 3466.33,2473.77 v1(3485.83,2493.27) ; R88.1@4107.62,2737 4108.23,2736.39 4108.23,2716.77 v1(4127,2698)
MCU_GPIO165: R126.1 R128.2 U1.F6 | length 2494.3
  Top Layer w5: v2(3395.33,2188.77) U1.F6@3411.08,2173.03 ; v1(4485.83,3085.27) 4485.83,3051.22 R126.1@4496.74,3040.31
  Signal Layer 3 w5: v1(3498.57,3046) 3620,3046 3657.77,3083.77 3977.64,3083.77 3990.14,3071.27 4424.27,3071.27 4444,3091 4475.5,3091 4481.23,3085.27 v1(4485.83,3085.27)
  Signal Layer 6 w5: v2(3395.33,2188.77) 3411.33,2204.77 3411.33,2292.16 3366.4,2337.09 3366.4,2447.16 3307.22,2506.33 3307.22,2570.22 3357,2620 3357,3016.55 3396.45,3056 3488.57,3056 v1(3498.57,3046)
  Bottom w5: v1(4485.83,3085.27) 4525.1,3046 4758.73,3046 4772.32,3059.59 R128.2@4807.68,3059.59
MCU_GPIO166: R113.2 R116.1 U1.B5 | length 2274.2
  Top Layer w5: U1.B5@3379.58,2299.01 3363.83,2314.76 3363.83,2360.54 3350.83,2373.54 3350.83,2438.27 v1(3413.83,2501.27) ; v1(4528.83,3082.27) 4528.83,3081.14 4538.83,3071.14 R116.1@4538.83,3037.25
  Signal Layer 3 w5: v1(3581,3065) 3608.77,3092.77 3967.33,3092.77 3982.99,3108.43 4010.57,3108.43 4038.73,3080.27 4420.54,3080.27 4444.04,3103.77 4507.33,3103.77 v1(4528.83,3082.27)
  Signal Layer 6 w5: v1(3413.83,2501.27) 3492.83,2580.27 3492.83,2788.42 3555.09,2850.68 3555.09,2904.09 3631.53,2980.53 3631.53,3017.29 3583.82,3065 v1(3581,3065)
  Bottom w5: v1(4528.83,3082.27) 4556.1,3055 4755,3055 R113.2@4807.81,3107.81
MCU_GPIO167: R111.1 R117.1 U1.E5 | length 2476.1
  Top Layer w5: v2(3363.83,2220.27) U1.E5@3379.58,2204.52 ; R111.1@4585.38,3231 4585.38,3101.72 v1(4585.83,3101.27) R117.1@4585.83,3043.36
  Signal Layer 6 w5: v2(3363.83,2220.27) 3348.33,2235.77 3348.33,2294.77 3341.83,2301.27 3341.83,2446.27 3281.33,2506.77 3281.33,2783.6 3339,2841.27 3339,2947.27 3290.83,2995.44 3290.83,3064.1 3332.23,3105.5 3581.5,3105.5 3618,3142 4545.1,3142 v1(4585.83,3101.27)
MCU_GPIO168: R89.1 R118.1 U1.F5 | length 2551.8
  Top Layer w5: v2(3363.83,2188.77) U1.F5@3379.58,2173.03 ; R118.1@4630.62,3047.89 4629.83,3048.68 v1(4629.83,3078.27) 4643.38,3091.82 R89.1@4643.38,3231
  Signal Layer 6 w5: v2(3363.83,2188.77) 3379.33,2204.27 3379.33,2298 3355,2322.33 3355,2445.83 3294.57,2506.26 3294.57,2612.78 3290.33,2617.02 3290.33,2779.88 3348,2837.54 3348,2951 3299.83,2999.17 3299.83,3060.38 3335.96,3096.5 3790.56,3096.5 3825.83,3131.77 4508.33,3131.77 4561.83,3078.27 v1(4629.83,3078.27)
MCU_GPIO222/TDI: EC1.8 U1.T12 U7.3 | length 4656.4
  Top Layer w5: v1(3035,2614) 3033.92,2615.08 3019.92,2615.08 3004,2631 3004,2695.79 3017.56,2709.35 U7.3@3062.54,2709.35 ; v1(3591.09,1559.68) 3600.06,1568.64 U1.T12@3600.06,1858.07
  Signal Layer 3 w5: v1(3035,2614) 3035,2612.61 2952.83,2530.44 2952.83,2310.83 2684.27,2042.27 1939.27,2042.27 1840,1943 1840,1645 2024,1461 2024,1335 2107.42,1251.58 2122.42,1251.58 v1(2124,1250) 2460.18,1250 2788.68,1578.5 3012.29,1578.5 3048.52,1542.27 3296.31,1542.27 3318.93,1519.64 3551.06,1519.64 v1(3591.09,1559.68)
  Bottom w5: v1(2124,1250) 2126.87,1247.13 2126.87,1192.73 2140.04,1179.56 EC1.8@2140.04,1135.27
MCU_GPIO223/TDO: EC1.6 U1.R12 U7.12 | length 4888.8
  Top Layer w5: v1(3520.87,1591.69) 3522.22,1590.33 3535.68,1590.33 3586.02,1540 3606,1540 3615.43,1549.43 3615.43,1874.19 U1.R12@3600.06,1889.56
  Top Layer w6.25: U7.12@3287.01,2709.43 3287.32,2709.74 3328.31,2709.74 v1(3328.83,2710.27)
  Signal Layer 3 w5: v1(3328.83,2710.27) 3332.29,2710.27 3361.83,2680.73 3361.83,2623.75 3290.58,2552.5 3210.5,2552.5 3081,2423 3081,2400.82 2695.45,2015.27 1954.45,2015.27 1867,1927.82 1867,1656.18 2052,1471.18 2052,1399.6 2083.6,1368 v1(2085,1368) 2102,1351 2523,1351 2777.73,1605.73 3024.51,1605.73 3060.98,1569.27 3307.49,1569.27 3330.11,1546.64 3475.83,1546.64 v1(3520.87,1591.69)
  Bottom w5: v1(2085,1368) 2086.5,1366.5 2086.5,1244.5 2109.61,1221.39 EC1.6@2109.61,1138.69
MCU_TCK: EC1.5 U1.R13 U7.8 | length 4737.7
  Top Layer w5: EC1.5@2108.54,1135.27 2102,1141.81 2102,1310 v1(2114,1322) ; U7.8@3287.01,2646.44 3284.83,2644.26 3284.83,2632.27 3292.83,2624.27 v1(3307.83,2624.27) ; U1.R13@3631.55,1889.56 3646.93,1874.19 3646.93,1750.38 3661.15,1736.15 3661.15,1709.59 3649.86,1698.29 v1(3644.81,1698.29)
  Signal Layer 3 w5: v1(3307.83,2624.27) 3254.56,2571 3228.11,2571 3227.61,2570.5 3203.04,2570.5 3060.5,2427.95 3060.5,2405.77 2688,2033.27 1947,2033.27 1849,1935.27 1849,1648.73 2034,1463.73 2034,1343 2055,1322 v1(2114,1322) 2519.46,1322 2784.96,1587.5 2797.5,1587.5 2797.73,1587.73 3015.79,1587.73 3052.25,1551.27 3300.04,1551.27 3322.66,1528.64 3534.37,1528.64 3631.83,1626.1 3631.83,1685.32 v1(3644.81,1698.29) ; v1@3647.33,1695.77 v1@3649.83,1698.27
MCU_TMS: EC1.3 R202.1 U1.T13 U7.6 | length 5223.5
  Top Layer w5: v1(2069,1340) 2069,1143.32 EC1.3@2077.05,1135.27 ; U7.6@3054.73,2662.19 3109.81,2662.19 3124,2648 3124,2604.7 3114.83,2595.53 v1(3114.83,2593.27) ; U1.T13@3631.55,1858.07 3631.55,1739.4 3640.74,1730.2 v1(3640.74,1725.6)
  Signal Layer 3 w5: v1(2069,1340) 2524.73,1340 2781.46,1596.73 3020.79,1596.73 3057.25,1560.27 3303.76,1560.27 3326.39,1537.64 3530.64,1537.64 3622.83,1629.83 3622.83,1707.69 v1(3640.74,1725.6) ; v1@2069.5,1339.5 2043,1366 2043,1467.46 1858,1652.46 1858,1931.54 1950.72,2024.27 2691.72,2024.27 3072,2404.54 3072,2426.73 3206.77,2561.5 3285.44,2561.5 3352.83,2628.9 3352.83,2652.02 3337.85,2667 3161.16,2667 3114.83,2620.68 v1(3114.83,2593.27)
  Bottom w5: v1(3640.74,1725.6) 3641.89,1726.75 3680.41,1726.75 3703.86,1703.3 3725.9,1703.3 3747.31,1724.69 R202.1@3750.87,1724.69
MCU_XRSn: C38.1 EC1.120 R42.1 R44.1 R49.1 R55.1 R82.1 S4.4 TP17.1 U1.G14 | length 3456.4
  Top Layer w5: U1.G14@3663.05,2141.53 v2(3678.79,2157.28) ; S4.4@3884.32,3231.44 3947.56,3231.44 4000.73,3178.27 4219.83,3178.27 4232.33,3165.77 R49.1@4232.33,3150.27 4261.83,3120.76 4261.83,3043.27 4243.34,3024.77 4231.13,3024.77 4231.13,3024.97 4200.83,3055.27 4145.83,3055.27 4140.07,3049.51 4140.07,2896.77 4132.57,2889.27 4080.33,2889.27 R44.1@4048.83,2857.77 4048.83,2801.95 v1(4070.79,2779.99) ; TP17.1@3925.83,2239.27 3965.1,2200 R82.1@3999.21,2200
  Signal Layer 6 w5: v1@4074.83,2780.27 4087.83,2767.27 4103.33,2751.77 4103.33,2675.02 4079.81,2651.5 4079.81,2327.25 4017.33,2264.77 3951.33,2264.77 TP17.1@3925.83,2239.27 3934.44,2230.66 3952.09,2230.66 4002.34,2180.41 4079.59,2103.15 4079.59,1993.72 4099,1974.31 4099,1882.05 4099.33,1881.72 4099.33,1764.6 4099,1764.27 4099,1710.1 4128.5,1680.6 4128.5,1394.5 v1(4088,1354)
  Bottom w5: v2(3678.79,2157.28) 3681.28,2154.79 3687.7,2154.79 3688.22,2154.27 3855.27,2154.27 3915.07,2214.07 3915.07,2216.33 3917.22,2218.48 3917.22,2230.66 TP17.1@3925.83,2239.27 ; EC1.120@4029.8,1135.27 4023,1142.07 4023,1289 v1(4088,1354) 4067,1354 4050,1371 C38.1@4050,1399.38 4097.24,1446.62 R42.1@4098,1446.62
MID_RXD: S1.3 U6.14 | length 345.4
  Top Layer w5: U6.14@2956.44,2645.69 2958.5,2643.63 2976.26,2643.63 3027.12,2592.77 3078.23,2592.77 v1(3083,2588)
  Bottom w5: v1(3083,2588) 3106.01,2611.01 3124,2611.01 3132.54,2602.47 3251.09,2602.47 S1.3@3260.87,2592.69
MID_TCK_SWDCLK: U6.12 U7.9 | length 495.8
  Top Layer w5: U6.12@2956.44,2595.69 2980.02,2595.69 2984.24,2591.47 2984.63,2591.47 3018.83,2557.27 3090.81,2557.27 v1(3101.82,2568.27) ; U7.9@3287.01,2662.19 3323.41,2662.19 3330.83,2654.77 3330.83,2638.27 v1(3332.83,2636.27)
  Signal Layer 3 w5: v1(3101.82,2568.27) 3146.81,2568.27 3158.54,2580 3238.81,2580 3300.58,2641.77 3307.83,2641.77 3327.33,2641.77 v1(3332.83,2636.27)
MID_TDI: U6.15 U7.2 | length 133.8
  Top Layer w5: U6.15@2956.44,2670.69 2988.25,2670.69 2994.83,2677.26 2994.83,2699.34 3020.67,2725.18 U7.2@3054.73,2725.18
MID_TDO_SWO: U6.10 U7.11 | length 587.3
  Top Layer w5: U6.10@2956.44,2545.69 3002.14,2545.69 3009.56,2538.27 3304.27,2538.27 3331.27,2565.27 3359.83,2593.83 3359.83,2654.73 3320.87,2693.69 U7.11@3287.01,2693.69 U7.11@3279.01,2693.69
MID_TMS_JTAG: U6.11 U7.5 | length 376.1
  Top Layer w5: U6.11@2956.44,2570.69 2989.87,2570.69 3013.29,2547.27 3108.46,2547.27 3134.87,2573.69 3134.87,2651.69 3108.62,2677.94 U7.5@3046.73,2677.94
NetB1_2: B1.2 R73.2 R74.1 | length 249.7
  Bottom w5: B1.2@5061.29,2589.89 5131.7,2589.89 5183.44,2641.62 5183.44,2698.79 R73.2@5134.44,2698.79
NetB1_3: B1.3 R65.1 | length 132.5
  Bottom w5: B1.3@5061.29,2615.48 5094.38,2615.48 5110.84,2631.94 5110.84,2673.55 5091.23,2693.16 R65.1@5084.44,2693.16
NetB1_5: B1.5 R68.1 | length 100
  Bottom w5: R68.1@5232.44,2693.16 5232.44,2663.69 5255.05,2641.07 B1.5@5293.58,2641.07
NetB1_8: B1.8 R67.1 | length 83.9
  Bottom w5: B1.8@5298.28,2569 B1.8@5293.58,2564.3 5345.51,2564.3 R67.1@5363.44,2546.37
NetC1_1: C1.1 R7.2 U2.96 | length 222.7
  Top Layer w5: v1(2243.87,2800.69) 2273.87,2800.69 2316.25,2800.69 R7.2@2317.87,2802.31
  Bottom w6.25: U2.96@2107.7,2829.35 2215.21,2829.35 v1(2243.87,2800.69)
NetC10_1: C10.1 C11.1 C12.1 U2.87 U2.115 | length 654.3
  Bottom w6.25: U2.87@2107.7,2687.62 2332.62,2687.62 2450.22,2805.22 U2.115@2450.22,2888.41 2450.22,2946.57 C11.1@2468.09,2964.44 2469.09,2965.44 C10.1@2564.09,2965.44
NetC13_1: C13.1 U2.89 Y1.3 | length 268.5
  Bottom w5: Y1.3@1919.37,2852.99 1919.37,2832.05 1940.73,2810.69 1998.25,2810.69 2008.62,2800.31 2012.56,2800.31 2021.87,2791 C13.1@2021.87,2787.06 2027.87,2781.06 2027.87,2763.69 2072.44,2719.12 U2.89@2107.7,2719.12
NetC14_1: C14.1 U2.88 Y1.1 | length 418
  Bottom w6.25: Y1.1@1856.38,2766.38 1841.99,2752 1841.99,2733.11 1877.1,2698 1932.19,2698 1972.87,2738.69 C14.1@1972.87,2786.69 ; C14.1@1973.87,2787.06 2057.25,2703.69 U2.88@2107.87,2703.69
NetC15_1: C15.1 R13.1 U2.68 | length 217.1
  Bottom w5: C15.1@1988.87,2454.31 2012.12,2431.06 2052.49,2431.06 2064.87,2418.69 2064.87,2392.07 2068.53,2388.41 U2.68@2107.7,2388.41 ; C15.1@1988.87,2454.69 R13.1@1988.87,2510.06
NetC19_1: C19.1 U8.4 | length 111
  Top Layer w5: U8.4@2028.05,2483.28 2059.27,2483.28 2070.87,2471.69 C19.1@2070.87,2408.31
NetC39_1: C39.1 U11.3 | length 69.2
  Top Layer w6.25: C39.1@3759.11,2986 C39.1@3767.62,2986 3780.04,2973.58 U11.3@3823.17,2973.58
NetC41_1: C41.1 R51.1 U12.2 | length 694.7
  Top Layer w5: v1(3889,3066) 3893.6,3066 3901.97,3074.37 3935.97,3074.37 U12.2@3936.81,3073.53 ; R51.1@3983.87,2651.06 4009.94,2651.06 4029.7,2631.3 v1(4029.7,2608.75) 4045.83,2592.62 C41.1@4068,2592.62
  Signal Layer 6 w5: v1(3889,3066) 3973,2982 3973,2665.45 v1(4029.7,2608.75) ; v1@4029.7,2606.25 v1@4035.75,2606.25
NetC42_1: C42.1 R54.1 U12.4 | length 665.9
  Top Layer w5: v1(3902.83,3023.27) 3907.09,3023.27 3917.03,3033.2 3937.39,3033.2 U12.4@3938.87,3034.69 ; R54.1@3936.87,2651.06 3936.87,2613.13 3958,2592 3981.38,2592 C42.1@3983,2593.62 3993.62,2583 v1(4021,2583)
  Signal Layer 6 w5: v1(3902.83,3023.27) 3964,2962.1 3964,2640 v1(4021,2583)
NetC48_1: C48.1 R30.1 R95.2 R97.2 | length 385.9
  Bottom w5: C48.1@5502.44,1695.21 5502.44,1706.69 5527.94,1732.19 5591.36,1732.19 R30.1@5618.44,1705.11 ; R95.2@5618.44,1657.83 R30.1@5618.44,1705.11 ; R97.2@5618.44,1798.69 5653.44,1798.69 5686.44,1765.69 5686.44,1740.69 5650.86,1705.11 R30.1@5618.44,1705.11
NetC48_2: C48.2 C49.1 L1.2 R2.1 R30.2 R94.2
NetC50_1: C50.1 R102.1 R206.2 U15.1 | length 309.2
  Top Layer w5: v1(5476,1893) 5544.75,1961.75 5554.75,1961.75 v1(5558,1965)
  Bottom w5: U15.1@5445.28,1870.37 5452.66,1870.37 5475.29,1893 v1(5476,1893) ; C50.1@5502.44,2004.16 5508.19,1998.4 R206.2@5571.19,1998.4 ; v1(5558,1965) 5571.19,1978.19 R206.2@5571.19,1998.4 ; R102.1@5571.19,2045.69 R206.2@5571.19,1998.4
NetC50_2: C50.2 C125.1 L2.2 R101.1 R102.2
NetC52_1: C52.1 R99.1 U15.8 | length 151.8
  Bottom w5: C52.1@5261.19,1875.69 R99.1@5261.19,1827.69 5264.5,1831 U15.8@5363.59,1831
